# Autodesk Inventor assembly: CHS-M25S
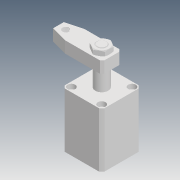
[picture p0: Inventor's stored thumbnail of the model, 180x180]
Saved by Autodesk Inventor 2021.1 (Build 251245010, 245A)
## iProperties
Created: 2019-05
Part Number: CHS-M25S
Description: STEP AP203
Document SubType Name: Assembly
Designer: user
Title: chs-m25s_asm.STEP
Revision Number: ÈÎºÎ
Sending System: SolidWorks 2017
Preprocessor: SwSTEP 2.0
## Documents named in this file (5)
- D:\Vault_2016\Projekty\Clamptek\Hydraulic\CHS\CHS-25\Inventor\CHS-M25S\CHS-M25S.iam
- D:\Vault_2016\Projekty\Clamptek\Hydraulic\CHS\CHS-25\Inventor\CHS-M25S\CHS-M25-03_1.ipt
- D:\Vault_2016\Projekty\Clamptek\Hydraulic\CHS\CHS-25\Inventor\CHS-M25S\CHS-25S-02_5_1.ipt
- D:\Vault_2016\Projekty\Clamptek\Hydraulic\CHS\CHS-25\Inventor\CHS-M25S\CHS-25-01.ipt
- D:\Vault_2016\Projekty\Clamptek\Hydraulic\CHS\CHS-25\Inventor\CHS-M25S\M14_5.ipt
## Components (4 placed, 4 different names)
1. CHS-M25-03_1_1
2. CHS-25S-02_5_1_2
3. CHS-25-01_3
4. M14_5_4
